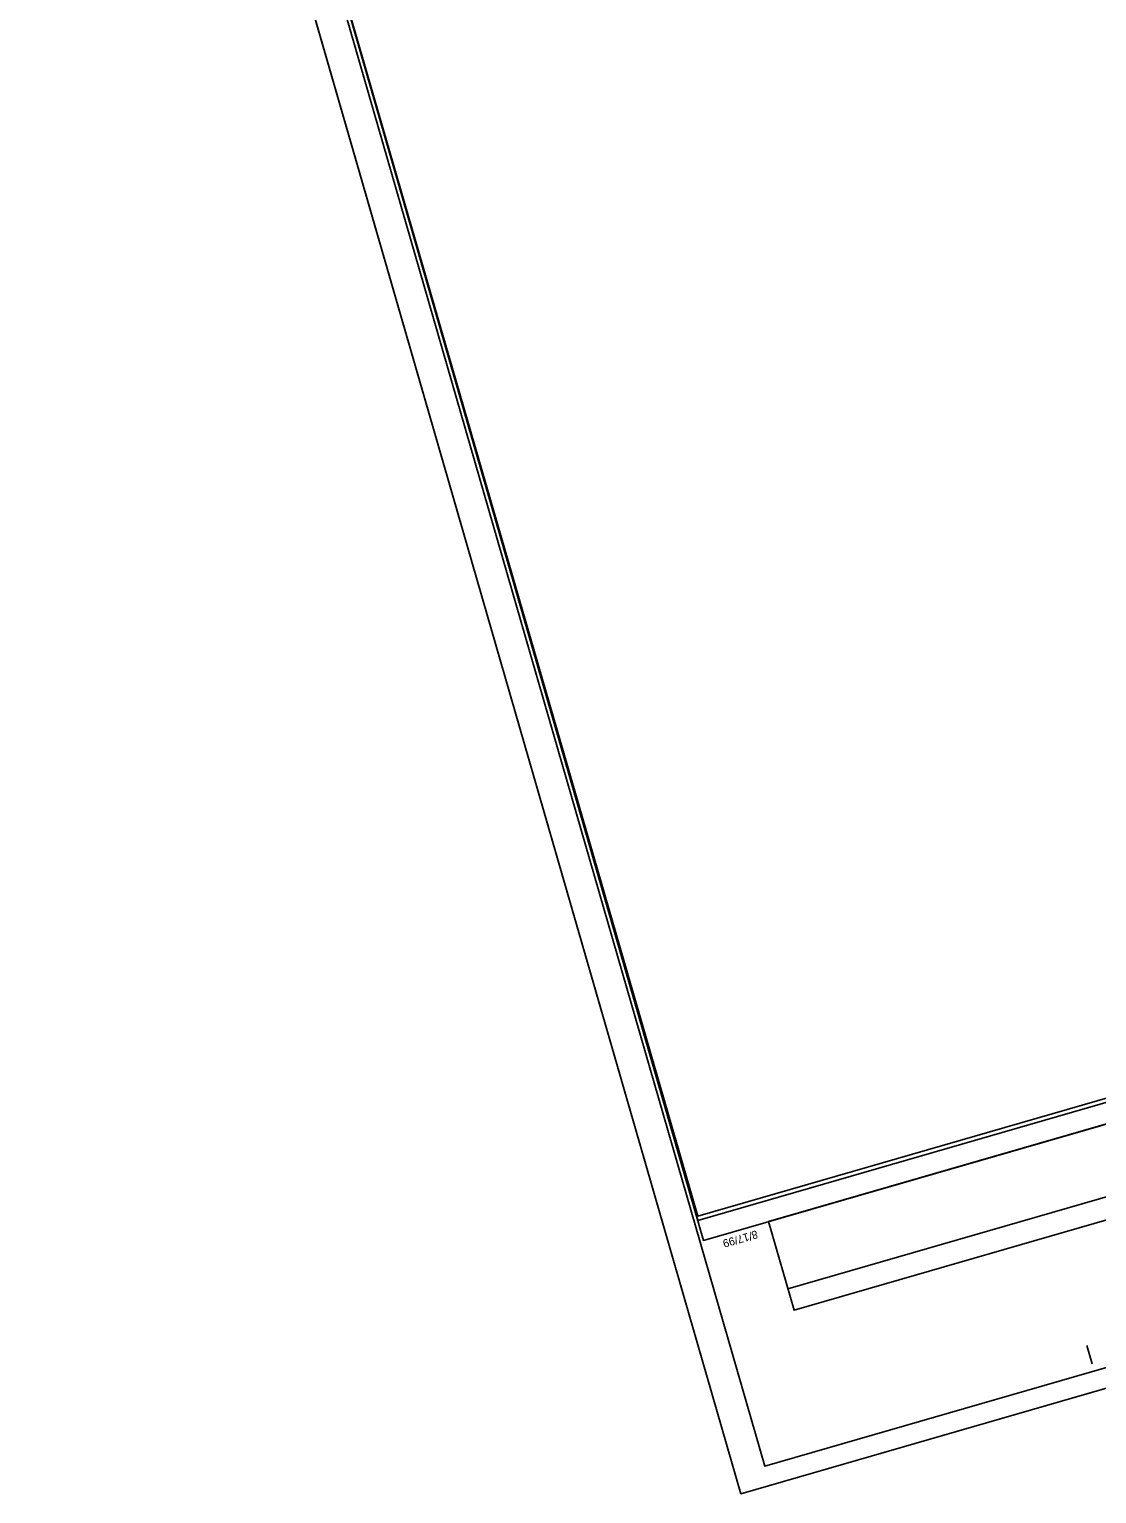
# Model space of a CAD drawing. Extents: x 2167139 to 2168658, y 842502 to 844423.
# Drawn here: x 2167139 to 2167839, y 842502 to 843463 of the extents above; entities that cross this region are included whole.
import ezdxf

# ---------------------------------------------------------------- set-up
doc = ezdxf.new("R2010")
doc.units = 0
for name, color, linetype in [('Sheet Block Revision CELL', 7, 'Continuous'), ('Sheet Clip Boundary CELL', 7, 'Continuous'), ('Sheet Cutting Line CELL', 7, 'Continuous'), ('Sheet Layout Plan Border', 7, 'Continuous'), ('Sheet Plan CELL', 7, 'Continuous'), ('Sheet Plan Layout CELL', 7, 'Continuous'), ('Sheet Plot Border Inside CELL', 7, 'Continuous'), ('Sheet Plot Border Outside CELL', 7, 'Continuous')]:
    doc.layers.add(name, color=color, linetype=linetype)

msp = doc.modelspace()

# ---------------------------------------------------------------- linework, layer by layer
at = {"layer": 'Sheet Block Revision CELL'}
msp.add_line((2168396.31, 842855.61), (2167636.7, 842636.29), dxfattribs=at)
msp.add_lwpolyline([(2168400.37, 842841.64), (2167640.74, 842622.33), (2167623.93, 842680.48), (2168383.55, 842899.8)], close=True, dxfattribs=at)
at = {"layer": 'Sheet Clip Boundary CELL'}
msp.add_lwpolyline([(2168333.42, 842899.61), (2168359.34, 842906.72), (2168266.95, 843188.11), (2168382.06, 843220.66), (2168502.28, 843263.66), (2168187.91, 844352.53), (2167382.3, 844119.94), (2167434.8, 843938.11), (2167231.61, 843879.44), (2167577.57, 842681.16)], close=True, dxfattribs=at)
at = {"layer": 'Sheet Cutting Line CELL'}
for p, q in [((2167138.92, 844119.41), (2167605.9, 842501.98)), ((2167605.9, 842501.98), (2168657.93, 842805.71))]:
    msp.add_line(p, q, dxfattribs=at)
at = {"layer": 'Sheet Layout Plan Border'}
msp.add_lwpolyline([(2168586.35, 842975.21), (2168177.55, 844388.42), (2167371.94, 844155.82), (2167434.8, 843938.11), (2167231.61, 843879.44), (2167577.55, 842683.96)], close=True, dxfattribs=at)
at = {"layer": 'Sheet Plan CELL'}
for p, q in [((2167581.32, 842668.17), (2167581.32, 842668.17)), ((2167836.31, 842587.22), (2167832.81, 842599.23))]:
    msp.add_line(p, q, dxfattribs=at)
for points in [[(2167165.23, 844109.34), (2167581.32, 842668.17), (2168590.12, 842959.42), (2168174.04, 844400.57)], [(2168590.12, 842959.42), (2167581.35, 842668.15), (2167220.72, 843917.11), (2167364.89, 843958.75), (2167309.41, 844150.94), (2168174.04, 844400.57)]]:
    msp.add_lwpolyline(points, close=True, dxfattribs=at)
at = {"layer": 'Sheet Plan Layout CELL'}
msp.add_lwpolyline([(2167581.35, 842668.15), (2168590.12, 842959.42), (2168174.04, 844400.56), (2167368.43, 844167.97), (2167434.8, 843938.11), (2167231.61, 843879.44)], close=True, dxfattribs=at)
at = {"layer": 'Sheet Plot Border Inside CELL'}
msp.add_lwpolyline([(2168635.11, 842812.65), (2168172.98, 844413.26), (2167159.38, 844120.64), (2167621.51, 842520.01)], close=True, dxfattribs=at)
at = {"layer": 'Sheet Plot Border Outside CELL'}
msp.add_lwpolyline([(2168657.93, 842805.71), (2168190.95, 844423.15), (2167138.92, 844119.41), (2167605.9, 842501.98)], close=True, dxfattribs=at)

# ---------------------------------------------------------------- texts
at = {"layer": 'Sheet Plan CELL'}
msp.add_text('8/17/99', height=5.25, rotation=196.10421, dxfattribs=at).set_placement((2167616.06, 842674.84))

doc.saveas('drawing.dxf')
